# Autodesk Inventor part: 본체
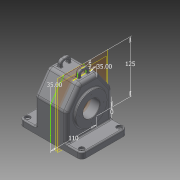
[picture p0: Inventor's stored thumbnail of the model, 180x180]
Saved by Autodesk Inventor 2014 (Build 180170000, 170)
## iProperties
Created: 2016-12
Part Number: 본체
Material: Generic
Document SubType Name: Modeling
Designer: user
Density: 1 g/cm^3
Appearance: Default
Author: user
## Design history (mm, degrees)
sketch "Sketch1"
  geometry: L1 (-75, 55)-(75, 55); L2 (75, 55)-(75, -55); L3 (75, -55)-(-75, -55); L4 (-75, -55)-(-75, 55); L5 (-75, 55)-(75, -55); L6 (75, 55)-(-75, -55); 1 further point
  constraints: 12 end point, 2 midpoint, 2 parallel, 1 horizontal, 1 perpendicular
  dimensions: "d0" = 150 distance of L2.end L3.end; "d1" = 110 distance of L1.end L2.end
extrude "Extrusion1" new body sketch "Sketch1" distance "d2" = 15; taper "d3" = 0 deg
sketch "Sketch2"
  geometry: L1 (-55, 15)-(55, 15) reference; L2 (55, 80)-(55, 0); L3 (55, 0)-(-55, 0); L4 (-55, 0)-(-55, 80); L5 (-55, 80)-(55, 0); L6 (55, 80)-(-55, 0); L7 (-55, 0)-(55, 0) reference; L8 (-55, 80)-(-23.491, 125); L9 (-23.491, 125)-(23.491, 125); L10 (23.491, 125)-(55, 80); 2 further points
  constraints: 16 end point, 2 midpoint, 2 parallel, 1 vertical alignment
  dimensions: "d4" = 110 distance of L2.end L3.end; "d6" = 0 distance between parallel lines of L3 L7; "d7" = 35 deg angle of L4 L8; "d8" = 35 deg angle of L2 L10; "d9" = 125 distance between parallel lines of L9 L3
extrude "Extrusion2" join sketch "Sketch2" stored distance "d10" = 77; taper "d11" = 0 deg
sketch "Sketch3"
  geometry: L1 (-50, 0)-(-50, 80); L2 (50, 0)-(50, 80); L3 (-55, 15)-(-55, 80) reference; L4 (55, 80)-(55, 15) reference; L5 (-20.888, 120)-(-50, 80); L6 (20.888, 120)-(50, 80); L7 (-20.888, 120)-(20.888, 120); L8 (-50, 0)-(50, 0); 1 further point
  constraints: 12 end point, 2 parallel, 1 perpendicular, 1 vertical
  dimensions: "d14" = 80 distance of L1.start L1.end; "d15" = 80 distance of L2.start L2.end; "d16" = 5 distance between parallel lines of L3 L1; "d17" = 5 distance between parallel lines of L4 L2
extrude "Extrusion3" cut sketch "Sketch3" stored distance "d18" = 67; taper "d19" = 0 deg
sketch "Sketch4"
  geometry: L1 (0, 55)-(0, -55) reference; C1 r 37.5 at (-65, 0); 2 further points
  constraints: 1 centre point, 1 horizontal alignment, 1 midpoint
  dimensions: "d20" = 75 diameter of C1; "d21" = 65 distance from line of C1.centre L1
extrude "Extrusion4" join sketch "Sketch4" distance "d22" = 5; taper "d23" = 0 deg
sketch "Sketch5"
  geometry: L1 (0, -55)-(0, 55) reference; C1 r 31 at (65, 0); 2 further points
  constraints: 1 centre point, 1 horizontal alignment, 1 midpoint
  dimensions: "d24" = 62 diameter of C1; "d25" = 65 distance from line of C1.centre L1
extrude "Extrusion5" join sketch "Sketch5" distance "d26" = 10; taper "d27" = 0 deg
sketch "Sketch6"
  geometry: L1 (-43.5, 102.5)-(-43.5, 27.5) reference; L2 (48.5, 34)-(48.5, 96) reference; L3 (-43.5, 65)-(48.5, 65); L4 (-33.5, 109.322)-(-16.178, 92); L5 (-16.178, 92)-(-16.178, 65); L6 (-33.5, 120)-(-33.5, 80) reference; L7 (-33.5, 109.322)-(-33.5, 65); 1 further point
  constraints: 8 end point, 3 point on line, 2 midpoint, 2 perpendicular
  dimensions: "d28" = 45 deg angle of L4 L5; "d29" = 54 diameter of L4.end L3
revolve "Revolution1" sketch "Sketch6" stored, may be unused: angle "d30" = 90 deg
sketch "Sketch7"
  geometry: C1 r 20 at (0, 0); 1 further point
  constraints: 1 centre point
  dimensions: "d31" = 40 diameter of C1
extrude "Extrusion6" cut sketch "Sketch7" stored distance "d32" = 10; taper "d33" = 0 deg
chamfer "Chamfer1" distance "d34" = 1; stored, may be unused: second distance "d35" = 2, angle "d36" = 45 deg
sketch "Sketch8"
  geometry: A1 r 29 centre (0, 0) between (0, 29) and (29, 0); 3 further points
  constraints: 4 point on circle, 1 centre point
  dimensions: "d37" = 58 diameter of A1
hole "Hole1" sketch "Sketch8" at (-29, 0), (0, 29), (29, 0), (0, -29) diameter "d38" = 2.459; stored, may be unused: countersink angle "d42" = 90 deg, drill point angle "d44" = 118 deg; dims "d39" = 6, "d40" = 4, "d41" = 2, "d43" = 8
sketch "Sketch9"
  geometry: A1 r 26 centre (0, 0) between (0, 26) and (26, 0); 3 further points
  constraints: 4 point on circle, 1 centre point
  dimensions: "d45" = 52 diameter of A1
hole "Hole2" sketch "Sketch9" at (26, 0), (0, -26), (-26, 0), (0, 26) diameter "d46" = 2.459; stored, may be unused: countersink angle "d50" = 90 deg, drill point angle "d52" = 118 deg; dims "d47" = 6, "d48" = 4, "d49" = 2, "d51" = 8
fillet "Fillet1" dims "d65" = 10
fillet "Fillet2" dims "d66" = 8
fillet "Fillet3" dims "d67" = 5
fillet "Fillet4" dims "d68" = 4
fillet "Fillet5" dims "d69" = 3
fillet "Fillet6" dims "d70" = 10
fillet "Fillet7" dims "d71" = 3
sketch "Sketch11"
  geometry: A1 r 10 centre (-65, 45) between (-65, 55) and (-75, 45) reference; A2 r 10 centre (65, 45) between (75, 45) and (65, 55) reference; A3 r 10 centre (65, -45) between (65, -55) and (75, -45) reference; A4 r 10 centre (-65, -45) between (-75, -45) and (-65, -55) reference; 5 further points
  constraints: 4 coincident
hole "Hole3" sketch "Sketch11" at (-65, 45), (-65, -45), (65, -45), (65, 45) diameter "d72" = 5; stored, may be unused: countersink angle "d76" = 90 deg, drill point angle "d78" = 0 deg; dims "d73" = 6, "d74" = 12, "d75" = 5, "d77" = 8
sketch "Sketch12"
  geometry: L1 (-34.5, 76.847)-(95.5, 76.847) reference; L2 (69, 0)-(69, 58.847) reference; 2 further points
  constraints: 1 other
  dimensions: "d79" = 45 distance from line of L1 point (30.5, 31.847); "d80" = 38.5 distance from line of point (30.5, 31.847) L2
emboss "Emboss1" sketch "Sketch12" dims "d10" = 77, "d11" = 0, "d81" = 0.5, "d82" = 0
fillet "Fillet8" dims "d83" = 3
workplane "Work Plane1"
sketch "Sketch13"
  geometry: L1 (-4.5, 140)-(4.5, 140); L2 (12.5, 132)-(12.5, 125); L3 (-12.5, 125)-(-12.5, 132); L4 (-12.5, 140)-(12.5, 122.977); L5 (12.5, 140)-(-12.5, 122.977); L6 (45, 0)-(-45, 0) reference; L7 (-3.5, 135)-(3.5, 135); L8 (7.5, 131)-(7.5, 125); L9 (-7.5, 125)-(-7.5, 131); L10 (-7.5, 135)-(7.5, 122.913); L11 (7.5, 135)-(-7.5, 122.913); L12 (-12.5, 125)-(12.5, 125); A1 r 4 centre (3.5, 131) between (7.5, 131) and (3.5, 135); A2 r 4 centre (-3.5, 131) between (-3.5, 135) and (-7.5, 131); A3 r 8 centre (4.5, 132) between (12.5, 132) and (4.5, 140); A4 r 8 centre (-4.5, 132) between (-4.5, 140) and (-12.5, 132); 7 further points
  constraints: 22 end point, 10 point on line, 8 point on circle, 8 tangent, 7 midpoint, 4 centre point, 3 perpendicular, 2 equal radius, 2 horizontal, 2 parallel, 2 vertical alignment, 1 coincident
  dimensions: "d86" = 25 distance of L4.end L5.end; "d87" = 140 distance between parallel lines of L6 L1; "d89" = 15 distance of L10.end L11.end; "d90" = 5 distance between parallel lines of L7 L1; "d91" = 4 radius of A1; "d92" = 8 radius of A3
extrude "Extrusion8" join sketch "Sketch13" distance "d93" = 8; taper "d94" = 0 deg
workplane "Work Plane2"
sketch "Sketch14"
  geometry: L1 (-125, 12.5)-(-132, 12.5) reference; L2 (-125, -7.5)-(-125, -12.5); L3 (-125, 12.5)-(-135, 12.5); L4 (-135, 12.5)-(-135, 7.485); L5 (-135, 7.485)-(-125, 7.485); L6 (-125, 7.485)-(-125, 12.5); L7 (-140, 4.5)-(-140, -4.5) reference; L8 (-125, -23.491)-(-125, 23.491) reference; L9 (-125, -7.5)-(-135, -7.5); L10 (-135, -7.5)-(-135, -12.5); L11 (-135, -12.5)-(-125, -12.5); L12 (-125, -12.5)-(-125, -7.5); 2 further points
  constraints: 18 end point, 4 parallel, 2 horizontal, 2 perpendicular
  dimensions: "d95" = 5 distance between parallel lines of L4 L7
mirror "Mirror1"
fillet "Fillet9" dims "d96" = 1
fillet "Fillet10" dims "d97" = 1
fillet "Fillet11" dims "d98" = 1
fillet "Fillet12" dims "d99" = 1
body "Solid1"
other parameters: "d84" = 18
